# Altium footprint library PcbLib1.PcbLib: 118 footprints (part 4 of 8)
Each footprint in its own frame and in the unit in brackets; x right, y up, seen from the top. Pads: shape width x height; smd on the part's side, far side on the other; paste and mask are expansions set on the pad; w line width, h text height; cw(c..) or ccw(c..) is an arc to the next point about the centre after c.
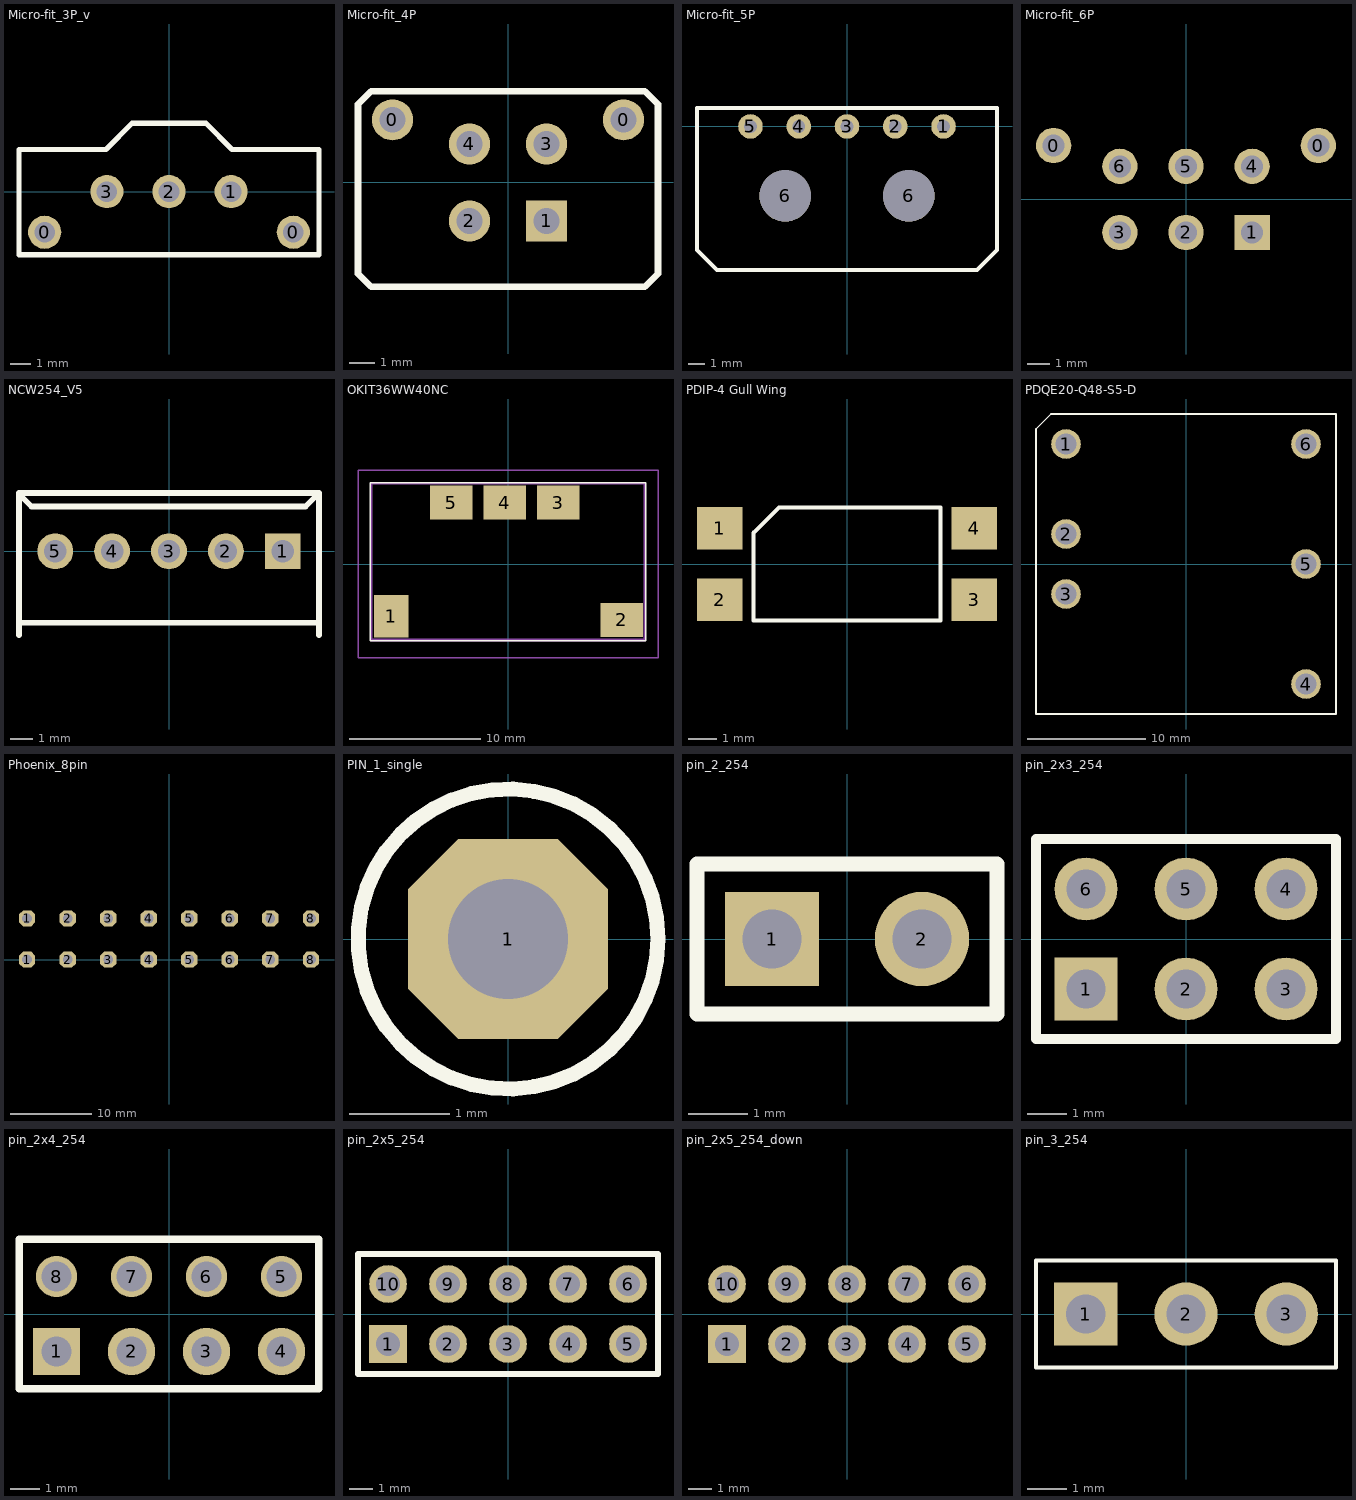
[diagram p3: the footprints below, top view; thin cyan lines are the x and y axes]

## Micro-fit_3P_v [mm] "vertical"
pads (5):
  round 1.6 hole 1: 0(-6,-1.96) 0(6,-1.96) 1(3,0) 2(0,0) 3(-3,0)
Top Overlay:
  lines w0.254: -7.239,-3.048 -7.239,2.032 -3.048,2.032 -1.778,3.302 1.778,3.302 3.048,2.032 7.239,2.032 7.239,-3.048 -7.239,-3.048
3D body "436500327.stp": height 9.95, standoff -3.13, extent -6.325,-2.47 6.325,3.135

## Micro-fit_4P [mm] "THT, double row, vertical"
pads (6):
  round 1.6 hole 1: 0(-4.5,2.44) 0(4.5,2.44) 2(-1.5,-1.5) 3(1.5,1.5) 4(-1.5,1.5)
  rect 1.6x1.6 hole 1: 1(1.5,-1.5)
Top Overlay:
  lines w0.254: -5.842,-3.556 -5.334,-4.064 5.334,-4.064 5.842,-3.556 5.842,3.048 5.334,3.556 -5.334,3.556 -5.842,3.048 -5.842,-3.556
3D body "430450428.stp": height 9.95, standoff -3.14, extent -5.075,-3.97 5.075,4.8

## Micro-fit_5P [mm] "horizontal"
pads (7):
  round 1.524 hole 0.8: 1(6,0) 2(3,0) 3(0,0) 4(-3,0) 5(-6,0)
  round 3.2 hole 3.2 unplated: 6(-3.84,-4.32) 6(3.84,-4.32)
Top Overlay:
  lines w0.254: -9.325,-7.675 -8.08,-8.92 8.08,-8.92 9.325,-7.675 9.325,1.143 -9.325,1.143 -9.325,-7.675
3D body "436500500.stp": height 5.64, standoff -3.27, extent -9.32,-8.887 9.32,1.013

## Micro-fit_6P [mm] "THT, double row, vertical"
pads (8):
  round 1.6 hole 1: 0(-6,2.44) 0(6,2.44) 2(0,-1.5) 3(-3,-1.5) 4(3,1.5) 5(0,1.5) 6(-3,1.5)
  rect 1.6x1.6 hole 1: 1(3,-1.5)
3D body "430450627.stp": height 9.95, standoff -3.14, extent -6.575,-3.97 6.575,4.8

## NCW254_V5 [mm]
pads (5):
  rect 1.6x1.6 hole 1: 1(5.08,0)
  round 1.6 hole 1: 2(2.54,0) 3(0,0) 4(-2.54,0) 5(-5.08,0)
Top Overlay:
  lines w0.254: -6.7,-3.74 -6.7,-3.2 ; -6.7,2.6 6.7,2.6 ; 6.7,-3.74 6.7,-3.2 ; -6.7,-3.2 6.7,-3.2 ; -6.7,-3.2 -6.7,2.56 -6.14,2 6.1,2 6.7,2.6 ; 6.7,-3.2 6.7,2.6
3D body "022112052.stp": height 10.68, standoff -3.54, extent -6.274,-3.302 6.274,3.048

## OKIT36WW40NC [mm]
pads (5):
  rect 2.6x3.24 smd: 1(-8.88,-3.975)
  rect 3.24x2.6 smd: 2(8.64,-4.255) 3(3.81,4.665) 4(-0.24,4.665) 5(-4.31,4.665)
Top Overlay:
  lines w0.1: -10.475,-5.825 10.475,-5.825 10.475,6.175 -10.475,6.175 -10.475,-5.825
Mechanical 15:
  lines w0.2: -10.4,-5.775 10.4,-5.775 10.4,6.125 -10.4,6.125 -10.4,-5.775
Mechanical 20:
  lines w0.1: -11.4,-7.125 11.4,-7.125 11.4,7.125 -11.4,7.125 -11.4,-7.125
3D body "mps_dcdc_oki_t36_a.STEP": height 8.55, standoff -0.04, extent -10.414,-5.842 10.414,6.096

## PDIP-4 Gull Wing [mm]
pads (4):
  rect 1.6x1.5 smd mask+0.08: 1(-4.5,1.27) 2(-4.5,-1.27) 3(4.5,-1.27) 4(4.5,1.27)
Top Overlay:
  lines w0.15: -3.3,-2 -3.3,1.1 -2.4,2 3.3,2 3.3,-2 -3.3,-2
3D body "PDIP-4_Gull_Wing.step": height 3.51, standoff 0.01, extent -5.08,-2.3 5.08,2.3

## PDQE20-Q48-S5-D [mm] "CUI DC-DC 5V@4A"
pads (6):
  round 2.5 hole 1.8: 1(-10.16,10.16) 2(-10.16,2.54) 3(-10.16,-2.54) 4(10.16,-10.16) 5(10.16,0) 6(10.16,10.16)
Top Overlay:
  lines w0.15: -12.7,-12.7 -12.7,11.43 -11.43,12.7 12.7,12.7 12.7,-12.7 -12.7,-12.7
3D body "CUI_PDQE20-Q48-S5-D.STEP": height 11.75, standoff -4.05, extent -12.7,-12.7 12.7,12.7

## Phoenix_8pin [mm]
pads (16):
  oct 2x2 hole 1.2 mask+0.05: 1(-17.5,0) 1(-17.5,5.08) 2(-12.5,0) 2(-12.5,5.08) 3(-7.5,0) 3(-7.5,5.08) 4(-2.5,0) 4(-2.5,5.08) 5(2.5,0) 5(2.5,5.08) 6(7.5,0) 6(7.5,5.08) 7(12.5,0) 7(12.5,5.08) 8(17.5,0) 8(17.5,5.08)

## PIN_1_single [mm]
pads (1):
  oct 2x2 hole 1.2: 1(0,0)
Top Overlay:
  circle w0.15: c0,0 r1.5
Bottom Overlay:
  circle w0.15: c0,0 r1.5

## pin_2_254 [mm]
pads (2):
  rect 1.6x1.6 hole 1: 1(-1.27,0)
  round 1.6 hole 1: 2(1.27,0)
Top Overlay:
  lines w0.254: -2.54,-1.27 2.54,-1.27 2.54,1.27 -2.54,1.27 -2.54,-1.27
3D body "header_2.STEP": height 8.6, standoff -3, extent -2.54,-1.27 2.54,1.27

## pin_2x3_254 [mm]
pads (6):
  rect 1.6x1.6 hole 1: 1(-2.54,-1.27)
  round 1.6 hole 1: 2(0,-1.27) 3(2.54,-1.27) 4(2.54,1.27) 5(0,1.27) 6(-2.54,1.27)
Top Overlay:
  lines w0.254: -3.81,-2.54 3.81,-2.54 3.81,2.54 -3.81,2.54 -3.81,-2.54
3D body "header_2x3.STEP": height 8.6, standoff -3, extent -3.81,-2.492 3.81,2.588

## pin_2x4_254 [mm]
pads (8):
  rect 1.6x1.6 hole 1: 1(-3.81,-1.27)
  round 1.6 hole 1: 2(-1.27,-1.27) 3(1.27,-1.27) 4(3.81,-1.27)
  round 1.4 hole 1: 5(3.81,1.27) 6(1.27,1.27) 7(-1.27,1.27) 8(-3.81,1.27)
Top Overlay:
  lines w0.254: -5.08,-2.54 -5.08,2.54 5.08,2.54 5.08,-2.54 -5.08,-2.54
3D body "header_2x4.STEP": height 8.6, standoff -3, extent -5.08,-2.54 5.08,2.54

## pin_2x5_254 [mm]
pads (10):
  rect 1.6x1.6 hole 1: 1(-5.08,-1.27)
  round 1.6 hole 1: 2(-2.54,-1.27) 3(0,-1.27) 4(2.54,-1.27) 5(5.08,-1.27) 6(5.08,1.27) 7(2.54,1.27) 8(0,1.27) 9(-2.54,1.27) 10(-5.08,1.27)
Top Overlay:
  lines w0.254: -6.35,-2.54 -6.35,2.54 6.35,2.54 6.35,-2.54 -6.35,-2.54
3D body "header_2x5.STEP": height 8.6, standoff -3, extent -6.35,-2.54 6.35,2.54

## pin_2x5_254_down [mm]
pads (10):
  rect 1.6x1.6 hole 1: 1(-5.08,-1.27)
  round 1.6 hole 1: 2(-2.54,-1.27) 3(0,-1.27) 4(2.54,-1.27) 5(5.08,-1.27) 6(5.08,1.27) 7(2.54,1.27) 8(0,1.27) 9(-2.54,1.27) 10(-5.08,1.27)
Bottom Overlay:
  lines w0.254: -6.35,-2.54 -6.35,2.54 6.35,2.54 6.35,-2.54 -6.35,-2.54
3D body "header_2x5.STEP": height 2.55, standoff -9.05, extent -6.35,-2.54 6.35,2.54

## pin_3_254 [mm]
pads (3):
  rect 1.6x1.6 hole 1: 1(-2.54,0)
  round 1.6 hole 1: 2(0,0) 3(2.54,0)
Top Overlay:
  lines w0.1: -3.8,-1.35 -3.8,1.35 3.8,1.35 3.8,-1.35 -3.8,-1.35
3D body "header_3.STEP": height 2.55, standoff -9.05, extent -3.81,-1.27 3.81,1.27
